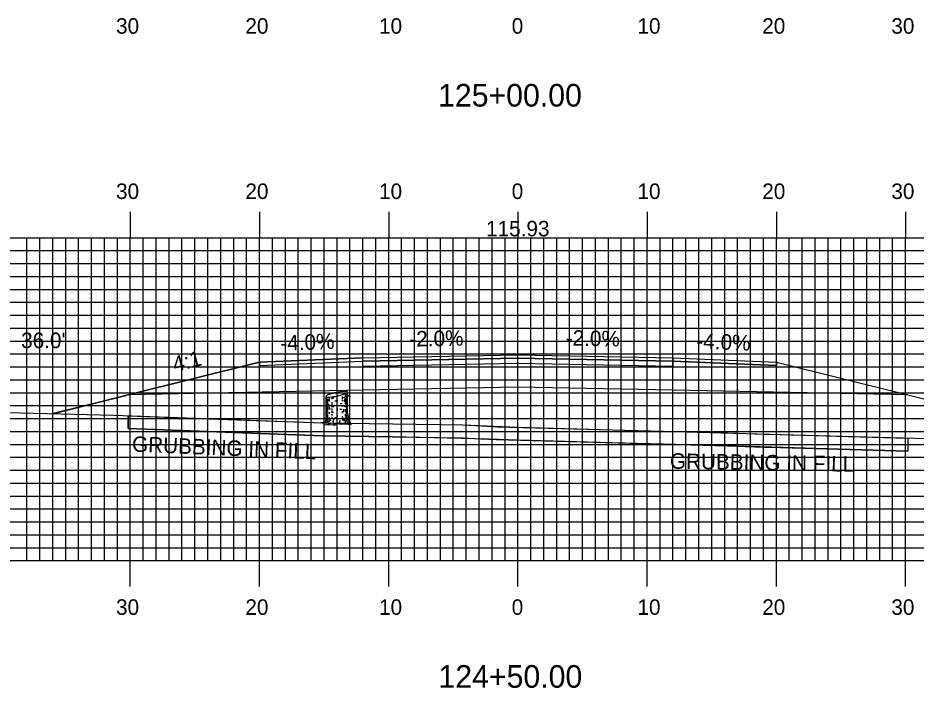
# Model space of a CAD drawing. Extents: x 1772809 to 1773153, y 442591 to 442811.
# Drawn here: x 1772936.4 to 1773005.9, y 442688.8 to 442740.7 of the extents above; entities that cross this region are included whole.
import ezdxf

# ---------------------------------------------------------------- set-up
doc = ezdxf.new("R2010")
doc.units = 0
for name, color, linetype in [('ANNOTATION', 7, 'Continuous'), ('D_Roadway_Centerline', 7, 'Continuous'), ('D_Roadway_Centerline_Text', 7, 'Continuous'), ('D_Roadway_Edge_Shoulder', 7, 'Continuous'), ('D_Roadway_Edge_TW', 7, 'Continuous'), ('D_Roadway_Pavement', 7, 'Continuous'), ('D_Roadway_SlopeLines', 7, 'Continuous'), ('D_Roadway_SubGrade', 7, 'Continuous'), ('D_Text_Standard', 7, 'Continuous'), ('GRUBBING IN FILL', 7, 'Continuous'), ('H_V ANNOTATION', 7, 'Continuous'), ('M_Trees_Conifer_Pay', 7, 'Continuous'), ('MAJOR', 7, 'Continuous'), ('MINOR', 7, 'Continuous'), ('S_Roadway_Centerline', 7, 'Continuous')]:
    doc.layers.add(name, color=color, linetype=linetype)

msp = doc.modelspace()

# ---------------------------------------------------------------- linework, layer by layer
at = {"layer": 'D_Roadway_Centerline'}
msp.add_lwpolyline([(1772939.158, 442710.043), (1772939.401, 442710.104), (1772943.12, 442711.034), (1772944.769, 442711.446), (1772944.946, 442711.49), (1772955.12, 442714.034), (1772963.12, 442714.354), (1772975.119, 442714.594), (1772987.12, 442714.354), (1772995.12, 442714.034), (1773005.294, 442711.49), (1773020.347, 442707.727)], dxfattribs=at)
at = {"layer": 'D_Roadway_Edge_Shoulder'}
for points in [[(1772963.12, 442714.354), (1772955.12, 442714.034), (1772955.12, 442713.784), (1772963.12, 442714.104)], [(1772987.12, 442714.354), (1772995.12, 442714.034), (1772995.12, 442713.784), (1772987.12, 442714.104)]]:
    msp.add_lwpolyline(points, close=True, dxfattribs=at)
at = {"layer": 'D_Roadway_Edge_TW'}
msp.add_lwpolyline([(1772963.12, 442714.104), (1772963.12, 442714.354), (1772975.119, 442714.594), (1772987.12, 442714.354), (1772987.12, 442714.104), (1772975.119, 442714.344)], close=True, dxfattribs=at)
at = {"layer": 'D_Roadway_Pavement'}
msp.add_lwpolyline([(1772963.12, 442713.687), (1772963.12, 442714.104), (1772975.119, 442714.344), (1772987.12, 442714.104), (1772987.12, 442713.687), (1772975.119, 442713.927)], close=True, dxfattribs=at)
at = {"layer": 'D_Roadway_SlopeLines'}
for points in [[(1772955.12, 442714.034), (1772944.946, 442711.49), (1772943.12, 442711.034), (1772939.158, 442710.043)], [(1772995.12, 442714.034), (1773005.294, 442711.49), (1773020.347, 442707.727)]]:
    msp.add_lwpolyline(points, dxfattribs=at)
at = {"layer": 'D_Roadway_SubGrade'}
msp.add_lwpolyline([(1772963.12, 442711.854), (1772944.946, 442711.49), (1772955.12, 442714.034), (1772955.12, 442713.784), (1772963.12, 442714.104), (1772975.119, 442714.344), (1772987.12, 442714.104), (1772995.12, 442713.784), (1772995.12, 442714.034), (1773005.294, 442711.49), (1772987.12, 442711.854), (1772975.119, 442712.094)], close=True, dxfattribs=at)
at = {"layer": 'GRUBBING IN FILL'}
for p, q in [((1772944.946, 442709.881), (1772944.946, 442708.881)), ((1772944.946, 442709.881), (1772944.946, 442708.881)), ((1773005.294, 442708.151), (1773005.294, 442707.151)), ((1773005.294, 442708.151), (1773005.294, 442707.151))]:
    msp.add_line(p, q, dxfattribs=at)
for points in [[(1772944.946, 442709.881), (1772951.924, 442709.628), (1772960.001, 442709.334), (1772965.43, 442709.25), (1772970.86, 442709.165), (1772975.12, 442708.99), (1772975.12, 442707.989), (1772972.856, 442708.067), (1772965.402, 442708.25), (1772959.975, 442708.335), (1772952.461, 442708.608), (1772944.946, 442708.881)], [(1772944.946, 442709.881), (1772951.924, 442709.628), (1772960.001, 442709.334), (1772965.43, 442709.25), (1772970.86, 442709.165), (1772975.12, 442708.99), (1772975.12, 442707.989), (1772972.856, 442708.067), (1772965.402, 442708.25), (1772959.975, 442708.335), (1772952.461, 442708.608), (1772944.946, 442708.881)], [(1772975.12, 442708.99), (1772982.42, 442708.791), (1772992.746, 442708.503), (1773000.682, 442708.278), (1773005.294, 442708.151), (1773005.294, 442707.151), (1772999.92, 442707.299), (1772991.302, 442707.549), (1772982.385, 442707.792), (1772975.12, 442707.989)], [(1772975.12, 442708.99), (1772982.42, 442708.791), (1772992.746, 442708.503), (1773000.682, 442708.278), (1773005.294, 442708.151), (1773005.294, 442707.151), (1772999.92, 442707.299), (1772991.302, 442707.549), (1772982.385, 442707.792), (1772975.12, 442707.989)]]:
    msp.add_lwpolyline(points, close=True, dxfattribs=at)
msp.add_lwpolyline([(1772944.946, 442708.881), (1772959.975, 442708.335), (1772970.829, 442708.166), (1772972.243, 442708.099), (1772973.468, 442708.034), (1772991.302, 442707.549), (1772994.141, 442707.457), (1772994.327, 442707.456), (1772994.546, 442707.446), (1773005.294, 442707.151)], dxfattribs=at)
msp.add_lwpolyline([(1772944.946, 442708.881), (1772959.975, 442708.335), (1772970.829, 442708.166), (1772972.243, 442708.099), (1772973.468, 442708.034), (1772991.302, 442707.549), (1772994.141, 442707.457), (1772994.327, 442707.456), (1772994.546, 442707.446), (1773005.294, 442707.151)], dxfattribs=at)
at = {"layer": 'M_Trees_Conifer_Pay'}
for p, q in [((1772960.269, 442709.656), (1772960.269, 442711.378)), ((1772960.317, 442711.341), (1772960.317, 442710.869)), ((1772960.375, 442711.329), (1772960.375, 442711.232)), ((1772960.375, 442711.158), (1772960.375, 442710.953)), ((1772960.5, 442711.322), (1772960.5, 442711.089)), ((1772960.72, 442711.342), (1772960.72, 442711.174)), ((1772961.126, 442711.11), (1772961.126, 442711.015)), ((1772961.516, 442711.384), (1772961.516, 442711.184)), ((1772961.516, 442711.127), (1772961.516, 442711.038)), ((1772961.744, 442711.58), (1772961.744, 442711.357)), ((1772961.744, 442711.268), (1772961.744, 442711.221)), ((1772961.802, 442711.085), (1772961.75, 442711.026)), ((1772961.862, 442711.641), (1772961.862, 442711.478)), ((1772961.862, 442711.411), (1772961.862, 442711.283)), ((1772961.862, 442711.096), (1772961.862, 442710.76)), ((1772961.933, 442710.066), (1772961.933, 442711.713)), ((1772960.317, 442710.805), (1772960.317, 442710.497)), ((1772960.317, 442710.449), (1772960.317, 442709.957)), ((1772960.375, 442710.896), (1772960.375, 442710.696)), ((1772960.375, 442710.649), (1772960.375, 442710.313)), ((1772960.5, 442711.049), (1772960.5, 442710.974)), ((1772960.5, 442710.571), (1772960.5, 442710.432)), ((1772960.72, 442710.937), (1772960.72, 442710.7)), ((1772960.72, 442710.455), (1772960.72, 442710.303)), ((1772961.126, 442710.497), (1772961.126, 442710.423)), ((1772961.126, 442710.398), (1772961.126, 442710.249)), ((1772961.516, 442710.69), (1772961.516, 442710.585)), ((1772961.744, 442710.886), (1772961.744, 442710.754)), ((1772961.744, 442710.643), (1772961.744, 442710.533)), ((1772961.744, 442710.398), (1772961.744, 442710.256)), ((1772961.862, 442710.723), (1772961.862, 442710.56)), ((1772961.862, 442710.513), (1772961.862, 442710.297)), ((1772960.317, 442709.904), (1772960.317, 442709.656)), ((1772960.375, 442710.26), (1772960.375, 442710.124)), ((1772960.375, 442710.025), (1772960.375, 442709.646)), ((1772960.5, 442710.161), (1772960.5, 442710.019)), ((1772960.5, 442709.757), (1772960.5, 442709.663)), ((1772960.72, 442710.26), (1772960.72, 442710.087)), ((1772960.72, 442709.809), (1772960.72, 442709.656)), ((1772961.126, 442709.957), (1772961.126, 442709.804)), ((1772961.516, 442710.219), (1772961.516, 442710.072)), ((1772961.516, 442709.84), (1772961.516, 442709.751)), ((1772961.744, 442710.029), (1772961.744, 442709.856)), ((1772961.862, 442710.266), (1772961.862, 442710.192)), ((1772961.862, 442710.151), (1772961.862, 442709.978)), ((1772960.5, 442709.263), (1772960.663, 442709.327)), ((1772960.937, 442709.199), (1772960.811, 442709.263))]:
    msp.add_line(p, q, dxfattribs=at)
for points in [[(1772961.717, 442711.174), (1772961.686, 442711.089), (1772961.682, 442711.022), (1772961.713, 442710.958)], [(1772961.75, 442711.211), (1772961.787, 442711.137), (1772961.834, 442711.194), (1772961.892, 442711.262), (1772961.985, 442711.456), (1772962.049, 442711.503), (1772962.08, 442711.51)], [(1772961.765, 442710.958), (1772961.802, 442711.085), (1772961.865, 442711.201), (1772961.896, 442711.268), (1772961.965, 442711.415)], [(1772961.979, 442711.444), (1772962.055, 442711.452), (1772962.127, 442711.353)], [(1772960.449, 442710.684), (1772960.443, 442710.779), (1772960.486, 442710.756), (1772960.486, 442710.661)], [(1772961.588, 442710.285), (1772961.6, 442710.208), (1772961.647, 442710.219), (1772961.635, 442710.385)], [(1772961.933, 442710.066), (1772961.985, 442709.804), (1772962.001, 442709.531), (1772962.059, 442709.406), (1772962.195, 442709.375), (1772961.964, 442709.337), (1772961.964, 442709.337), (1772961.97, 442709.29), (1772962.218, 442709.196), (1772961.943, 442709.212), (1772961.588, 442709.232), (1772961.266, 442709.222), (1772961.273, 442709.304), (1772961.124, 442709.222), (1772960.937, 442709.199), (1772960.962, 442709.131), (1772960.694, 442709.175), (1772960.473, 442709.148), (1772960.181, 442709.165), (1772960.47, 442709.222), (1772960.5, 442709.263), (1772960.338, 442709.321), (1772960.101, 442709.331), (1772959.86, 442709.331), (1772960.202, 442709.389), (1772960.243, 442709.469), (1772960.269, 442709.656)], [(1772961.76, 442709.778), (1772961.834, 442709.673), (1772961.839, 442709.5), (1772961.964, 442709.337)], [(1772961.859, 442709.924), (1772961.865, 442709.778), (1772961.912, 442709.71), (1772961.923, 442709.511)], [(1772960.317, 442709.609), (1772960.296, 442709.531), (1772960.276, 442709.436)], [(1772960.395, 442709.589), (1772960.401, 442709.473), (1772960.348, 442709.385), (1772960.338, 442709.321)], [(1772960.558, 442709.616), (1772960.558, 442709.484), (1772960.47, 442709.385)], [(1772960.784, 442709.375), (1772960.852, 442709.469), (1772960.879, 442709.609)], [(1772961.273, 442709.304), (1772961.347, 442709.446), (1772961.357, 442709.547)], [(1772961.523, 442709.673), (1772961.534, 442709.547), (1772961.608, 442709.504)], [(1772961.802, 442709.284), (1772961.787, 442709.422), (1772961.713, 442709.551)]]:
    msp.add_lwpolyline(points, dxfattribs=at)
for centre, radius, start, end in [((1772960.302, 442711.2), 0.0334, 163.94846, 180), ((1772960.302, 442711.2), 0.0334, 180, 196.05154), ((1772960.301, 442711.377), 0.0314, 156.51582, 169.2194), ((1772960.296, 442711.378), 0.0264, 169.2194, 180.03145), ((1772960.292, 442711.378), 0.0226, 180.03145, 191.7194), ((1772960.292, 442711.378), 0.0226, 191.7194, 203.40735), ((1772960.312, 442711.203), 0.0441, 196.05154, 210), ((1772960.296, 442711.379), 0.0264, 203.40735, 214.2194), ((1772960.32, 442711.368), 0.0527, 146.7194, 156.51582), ((1772960.3, 442711.382), 0.0314, 214.2194, 226.92298), ((1772960.328, 442711.212), 0.0624, 210, 228.74941), ((1772960.345, 442711.352), 0.0817, 132.38868, 146.7194), ((1772960.314, 442711.398), 0.0527, 226.92298, 236.7194), ((1772960.33, 442711.422), 0.0817, 236.7194, 251.05013), ((1772960.4, 442711.294), 0.172, 228.74941, 240), ((1772960.458, 442711.228), 0.251, 124.2194, 132.38868), ((1772960.385, 442711.582), 0.251, 251.05013, 259.2194), ((1772960.599, 442711.639), 0.571, 240, 240.33672), ((1772960.768, 442710.772), 0.802, 108.05939, 124.2194), ((1772960.488, 442712.123), 0.802, 259.2194, 275.37941), ((1772960.599, 442711.639), 0.571, 246.85973, 257.98457), ((1772962.125, 442706.61), 5.179, 101.7194, 108.05939), ((1772960.078, 442716.481), 5.179, 275.37941, 281.7194), ((1772961.102, 442715.39), 4.124, 264.6955, 266.73309), ((1772962.125, 442706.61), 5.179, 95.37941, 101.7194), ((1772960.078, 442716.481), 5.179, 281.7194, 288.05939), ((1772961.102, 442715.39), 4.124, 276.23804, 278.1032), ((1772961.715, 442710.968), 0.802, 79.2194, 95.37941), ((1772961.435, 442712.319), 0.802, 288.05939, 304.2194), ((1772961.603, 442711.872), 0.571, 278.1032, 284.36665), ((1772961.603, 442712.027), 0.571, 284.43166, 292.41325), ((1772961.603, 442711.872), 0.571, 297.0237, 300), ((1772961.818, 442711.51), 0.251, 71.05013, 79.2194), ((1772961.745, 442711.864), 0.251, 304.2194, 312.38868), ((1772961.802, 442711.682), 0.172, 300, 311.25059), ((1772961.802, 442711.527), 0.172, 300, 311.25059), ((1772961.873, 442711.669), 0.0817, 56.7194, 71.05013), ((1772961.858, 442711.739), 0.0817, 312.38868, 326.7194), ((1772961.874, 442711.599), 0.0624, 311.25059, 330), ((1772961.874, 442711.445), 0.0624, 311.25059, 330), ((1772961.889, 442711.694), 0.0527, 46.92298, 56.7194), ((1772961.903, 442711.709), 0.0314, 34.2194, 46.92298), ((1772961.883, 442711.723), 0.0527, 326.7194, 336.51582), ((1772961.89, 442711.59), 0.0441, 330, 343.94846), ((1772961.89, 442711.436), 0.0441, 330, 343.94846), ((1772961.907, 442711.712), 0.0264, 23.40735, 34.2194), ((1772961.902, 442711.714), 0.0314, 336.51582, 349.2194), ((1772961.911, 442711.713), 0.0226, 11.7194, 23.40735), ((1772961.9, 442711.587), 0.0334, 343.94846, 354.21506), ((1772961.9, 442711.433), 0.0334, 343.94846, 354.21506), ((1772961.911, 442711.713), 0.0226, 0.03145, 11.7194), ((1772961.907, 442711.713), 0.0264, 349.2194, 0.03145), ((1772960.302, 442710.753), 0.0334, 163.94846, 180), ((1772960.302, 442710.753), 0.0334, 180, 196.05154), ((1772960.302, 442710.543), 0.0334, 163.94846, 180), ((1772960.302, 442710.543), 0.0334, 180, 196.05154), ((1772960.312, 442710.756), 0.0441, 196.05154, 210), ((1772960.312, 442710.546), 0.0441, 196.05154, 210), ((1772960.328, 442710.765), 0.0624, 210, 228.74941), ((1772960.328, 442710.555), 0.0624, 210, 228.74941), ((1772960.4, 442710.848), 0.172, 228.74941, 240), ((1772960.4, 442710.638), 0.172, 228.74941, 240), ((1772960.599, 442711.193), 0.571, 240, 240.33672), ((1772960.599, 442710.983), 0.571, 240, 246.85973), ((1772960.601, 442711.428), 0.571, 240, 247.05866), ((1772960.599, 442710.983), 0.571, 259.27072, 261.8968), ((1772961.1, 442714.5), 4.124, 261.8968, 263.14738), ((1772961.1, 442714.71), 4.124, 264.08098, 266.66759), ((1772961.1, 442715.157), 4.124, 268.07512, 270), ((1772961.1, 442715.157), 4.124, 270, 270.35814), ((1772961.1, 442714.5), 4.124, 273.14934, 275.45691), ((1772961.102, 442714.946), 4.124, 273.70524, 275.95043), ((1772961.1, 442715.157), 4.124, 275.78493, 277.05584), ((1772961.1, 442714.71), 4.124, 277.61247, 278.1032), ((1772961.601, 442711.193), 0.571, 278.1032, 286.92962), ((1772961.602, 442711.428), 0.571, 284.44928, 297.04285), ((1772961.601, 442711.193), 0.571, 297.18959, 300), ((1772961.601, 442710.983), 0.571, 297.18959, 300), ((1772961.8, 442710.848), 0.172, 300, 311.25059), ((1772961.8, 442710.638), 0.172, 300, 311.25059), ((1772961.873, 442710.765), 0.0624, 311.25059, 330), ((1772961.873, 442710.555), 0.0624, 311.25059, 330), ((1772961.889, 442710.756), 0.0441, 330, 343.94846), ((1772961.889, 442710.546), 0.0441, 330, 343.94846), ((1772961.899, 442710.753), 0.0334, 343.94846, 354.21506), ((1772961.899, 442710.543), 0.0334, 343.94846, 354.21506), ((1772961.9, 442710.989), 0.0334, 343.94846, 354.21506), ((1772960.302, 442710.306), 0.0334, 163.94846, 180), ((1772960.302, 442710.306), 0.0334, 180, 196.05154), ((1772960.302, 442710.108), 0.0334, 163.94846, 180), ((1772960.302, 442709.913), 0.0334, 163.94846, 180), ((1772960.302, 442709.913), 0.0334, 180, 196.05154), ((1772960.302, 442709.693), 0.0334, 163.94846, 180), ((1772960.302, 442709.693), 0.0334, 180, 196.05154), ((1772960.312, 442710.309), 0.0441, 196.05154, 210), ((1772960.312, 442709.916), 0.0441, 196.05154, 210), ((1772960.328, 442710.318), 0.0624, 210, 228.74941), ((1772960.328, 442709.925), 0.0624, 210, 228.74941), ((1772960.4, 442710.401), 0.172, 228.74941, 240), ((1772960.4, 442710.008), 0.172, 228.74941, 240), ((1772960.599, 442710.746), 0.571, 240, 246.85973), ((1772960.589, 442710.554), 0.571, 241.23686, 248.02677), ((1772960.599, 442710.353), 0.571, 240, 246.85973), ((1772961.1, 442714.066), 4.124, 263.49906, 265.83975), ((1772961.1, 442714.263), 4.124, 264.71603, 266.31934), ((1772961.1, 442713.87), 4.124, 267.81166, 270), ((1772961.1, 442714.5), 4.124, 270, 270.35814), ((1772961.1, 442713.87), 4.124, 270, 270.13279), ((1772961.1, 442713.87), 4.124, 275.78493, 276.78961), ((1772961.601, 442710.746), 0.571, 285.39827, 297.18959), ((1772961.601, 442710.353), 0.571, 288.50673, 297.27208), ((1772961.601, 442710.548), 0.571, 289.29072, 300), ((1772961.8, 442710.203), 0.172, 300, 311.25059), ((1772961.873, 442710.121), 0.0624, 311.25059, 330), ((1772961.889, 442710.111), 0.0441, 330, 343.94846), ((1772961.899, 442710.108), 0.0334, 343.94846, 354.21506), ((1772961.899, 442709.693), 0.0334, 343.94846, 354.21506), ((1772960.312, 442709.696), 0.0441, 196.05154, 210), ((1772960.328, 442709.705), 0.0624, 210, 228.74941), ((1772960.4, 442709.787), 0.172, 228.74941, 240), ((1772960.599, 442710.132), 0.571, 240, 244.53138), ((1772961.1, 442713.65), 4.124, 262.44379, 263.51202), ((1772961.1, 442713.65), 4.124, 277.36842, 278.1032), ((1772961.601, 442710.132), 0.571, 278.1032, 281.63703), ((1772961.8, 442709.787), 0.172, 300, 311.25059), ((1772961.873, 442709.705), 0.0624, 311.25059, 330), ((1772961.889, 442709.696), 0.0441, 330, 343.94846)]:
    msp.add_arc(centre, radius, start, end, dxfattribs=at)
at = {"layer": 'MAJOR'}
for p, q in [((1772945.12, 442725.669), (1772945.12, 442723.665)), ((1772955.12, 442725.669), (1772955.12, 442723.665)), ((1772965.12, 442725.669), (1772965.12, 442723.665)), ((1772975.12, 442725.669), (1772975.12, 442723.665)), ((1772985.12, 442725.669), (1772985.12, 442723.665)), ((1772995.12, 442725.669), (1772995.12, 442723.665)), ((1773005.12, 442725.669), (1773005.12, 442723.665)), ((1772835.12, 442723.665), (1773115.12, 442723.665)), ((1772835.12, 442723.665), (1773115.12, 442723.665)), ((1772945.12, 442698.665), (1772945.12, 442723.665)), ((1772955.12, 442698.665), (1772955.12, 442723.665)), ((1772965.12, 442698.665), (1772965.12, 442723.665)), ((1772975.12, 442698.665), (1772975.12, 442723.665)), ((1772985.12, 442698.665), (1772985.12, 442723.665)), ((1772995.12, 442698.665), (1772995.12, 442723.665)), ((1773005.12, 442698.665), (1773005.12, 442723.665)), ((1772835.12, 442718.665), (1773115.12, 442718.665)), ((1772835.12, 442713.665), (1773115.12, 442713.665)), ((1772835.12, 442708.665), (1773115.12, 442708.665)), ((1772835.12, 442703.665), (1773115.12, 442703.665)), ((1772835.12, 442698.665), (1773115.12, 442698.665)), ((1772835.12, 442698.665), (1773115.12, 442698.665)), ((1772945.12, 442696.661), (1772945.12, 442698.665)), ((1772955.12, 442696.661), (1772955.12, 442698.665)), ((1772965.12, 442696.661), (1772965.12, 442698.665)), ((1772975.12, 442696.661), (1772975.12, 442698.665)), ((1772985.12, 442696.661), (1772985.12, 442698.665)), ((1772995.12, 442696.661), (1772995.12, 442698.665)), ((1773005.12, 442696.661), (1773005.12, 442698.665))]:
    msp.add_line(p, q, dxfattribs=at)
at = {"layer": 'MINOR'}
for p, q in [((1772937.12, 442698.665), (1772937.12, 442723.665)), ((1772938.12, 442698.665), (1772938.12, 442723.665)), ((1772939.12, 442698.665), (1772939.12, 442723.665)), ((1772940.12, 442698.665), (1772940.12, 442723.665)), ((1772941.12, 442698.665), (1772941.12, 442723.665)), ((1772942.12, 442698.665), (1772942.12, 442723.665)), ((1772943.12, 442698.665), (1772943.12, 442723.665)), ((1772944.12, 442698.665), (1772944.12, 442723.665)), ((1772946.12, 442698.665), (1772946.12, 442723.665)), ((1772947.12, 442698.665), (1772947.12, 442723.665)), ((1772948.12, 442698.665), (1772948.12, 442723.665)), ((1772949.12, 442698.665), (1772949.12, 442723.665)), ((1772950.12, 442698.665), (1772950.12, 442723.665)), ((1772951.12, 442698.665), (1772951.12, 442723.665)), ((1772952.12, 442698.665), (1772952.12, 442723.665)), ((1772953.12, 442698.665), (1772953.12, 442723.665)), ((1772954.12, 442698.665), (1772954.12, 442723.665)), ((1772956.12, 442698.665), (1772956.12, 442723.665)), ((1772957.12, 442698.665), (1772957.12, 442723.665)), ((1772958.12, 442698.665), (1772958.12, 442723.665)), ((1772959.12, 442698.665), (1772959.12, 442723.665)), ((1772960.12, 442698.665), (1772960.12, 442723.665)), ((1772961.12, 442698.665), (1772961.12, 442723.665)), ((1772962.12, 442698.665), (1772962.12, 442723.665)), ((1772963.12, 442698.665), (1772963.12, 442723.665)), ((1772964.12, 442698.665), (1772964.12, 442723.665)), ((1772966.12, 442698.665), (1772966.12, 442723.665)), ((1772967.12, 442698.665), (1772967.12, 442723.665)), ((1772968.12, 442698.665), (1772968.12, 442723.665)), ((1772969.12, 442698.665), (1772969.12, 442723.665)), ((1772970.12, 442698.665), (1772970.12, 442723.665)), ((1772971.12, 442698.665), (1772971.12, 442723.665)), ((1772972.12, 442698.665), (1772972.12, 442723.665)), ((1772973.12, 442698.665), (1772973.12, 442723.665)), ((1772974.12, 442698.665), (1772974.12, 442723.665)), ((1772976.12, 442698.665), (1772976.12, 442723.665)), ((1772977.12, 442698.665), (1772977.12, 442723.665)), ((1772978.12, 442698.665), (1772978.12, 442723.665)), ((1772979.12, 442698.665), (1772979.12, 442723.665)), ((1772980.12, 442698.665), (1772980.12, 442723.665)), ((1772981.12, 442698.665), (1772981.12, 442723.665)), ((1772982.12, 442698.665), (1772982.12, 442723.665)), ((1772983.12, 442698.665), (1772983.12, 442723.665)), ((1772984.12, 442698.665), (1772984.12, 442723.665)), ((1772986.12, 442698.665), (1772986.12, 442723.665)), ((1772987.12, 442698.665), (1772987.12, 442723.665)), ((1772988.12, 442698.665), (1772988.12, 442723.665)), ((1772989.12, 442698.665), (1772989.12, 442723.665)), ((1772990.12, 442698.665), (1772990.12, 442723.665)), ((1772991.12, 442698.665), (1772991.12, 442723.665)), ((1772992.12, 442698.665), (1772992.12, 442723.665)), ((1772993.12, 442698.665), (1772993.12, 442723.665)), ((1772994.12, 442698.665), (1772994.12, 442723.665)), ((1772996.12, 442698.665), (1772996.12, 442723.665)), ((1772997.12, 442698.665), (1772997.12, 442723.665)), ((1772998.12, 442698.665), (1772998.12, 442723.665)), ((1772999.12, 442698.665), (1772999.12, 442723.665)), ((1773000.12, 442698.665), (1773000.12, 442723.665)), ((1773001.12, 442698.665), (1773001.12, 442723.665)), ((1773002.12, 442698.665), (1773002.12, 442723.665)), ((1773003.12, 442698.665), (1773003.12, 442723.665)), ((1773004.12, 442698.665), (1773004.12, 442723.665)), ((1772835.12, 442722.665), (1773115.12, 442722.665)), ((1772835.12, 442721.665), (1773115.12, 442721.665)), ((1772835.12, 442720.665), (1773115.12, 442720.665)), ((1772835.12, 442719.665), (1773115.12, 442719.665)), ((1772835.12, 442717.665), (1773115.12, 442717.665)), ((1772835.12, 442716.665), (1773115.12, 442716.665)), ((1772835.12, 442715.665), (1773115.12, 442715.665)), ((1772835.12, 442714.665), (1773115.12, 442714.665)), ((1772835.12, 442712.665), (1773115.12, 442712.665)), ((1772835.12, 442711.665), (1773115.12, 442711.665)), ((1772835.12, 442710.665), (1773115.12, 442710.665)), ((1772835.12, 442709.665), (1773115.12, 442709.665)), ((1772835.12, 442707.665), (1773115.12, 442707.665)), ((1772835.12, 442706.665), (1773115.12, 442706.665)), ((1772835.12, 442705.665), (1773115.12, 442705.665)), ((1772835.12, 442704.665), (1773115.12, 442704.665)), ((1772835.12, 442702.665), (1773115.12, 442702.665)), ((1772835.12, 442701.665), (1773115.12, 442701.665)), ((1772835.12, 442700.665), (1773115.12, 442700.665)), ((1772835.12, 442699.665), (1773115.12, 442699.665))]:
    msp.add_line(p, q, dxfattribs=at)
at = {"layer": 'S_Roadway_Centerline'}
msp.add_lwpolyline([(1772930.628, 442710.207), (1772936.627, 442710.11), (1772943.848, 442709.921), (1772960.001, 442709.334), (1772970.86, 442709.165), (1772972.293, 442709.098), (1772973.509, 442709.034), (1772991.332, 442708.548), (1772994.16, 442708.457), (1772994.352, 442708.455), (1772994.581, 442708.446), (1773006.783, 442708.11), (1773017.015, 442707.813), (1773019.541, 442707.75), (1773022.485, 442707.665), (1773038.067, 442706.998), (1773042.223, 442706.935), (1773048.141, 442706.881)], dxfattribs=at)

# ---------------------------------------------------------------- texts
at = {"layer": 'ANNOTATION'}
for s, rotation, p in [('-4.0%', 2.29076, (1772956.752, 442714.901)), ('-2.0%', 1.1458, (1772966.726, 442715.227)), ('-2.0%', 358.85427, (1772978.806, 442715.321)), ('-4.0%', 357.70946, (1772988.911, 442715.084)), ('4:1', 14.03896, (1772948.569, 442713.258))]:
    msp.add_text(s, height=1.2, rotation=rotation, dxfattribs=at).set_placement(p)
at = {"layer": 'D_Roadway_Centerline'}
for s, p in [('C', (1772975.114, 442714.594)), ('L', (1772975.119, 442714.587))]:
    msp.add_text(s, height=0.0146, dxfattribs=at).set_placement(p)
at = {"layer": 'D_Roadway_Centerline_Text'}
msp.add_text('115.93', height=1.2, dxfattribs=at).set_placement((1772972.653, 442723.773))
at = {"layer": 'D_Text_Standard'}
msp.add_text("36.0'", height=1.2, dxfattribs=at).set_placement((1772936.671, 442715.12))
at = {"layer": 'GRUBBING IN FILL'}
for rotation, p in [(357.57187, (1772945.235, 442707.106)), (359.01917, (1772986.871, 442705.785))]:
    msp.add_text('GRUBBING IN FILL', height=1.2, rotation=rotation, dxfattribs=at).set_placement(p)
at = {"layer": 'H_V ANNOTATION'}
for s, height, p in [('30', 1.2, (1772944.017, 442739.465)), ('20', 1.2, (1772954.028, 442739.465)), ('10', 1.2, (1772964.37, 442739.465)), ('0', 1.2, (1772974.638, 442739.465)), ('10', 1.2, (1772984.37, 442739.465)), ('20', 1.2, (1772994.028, 442739.465)), ('30', 1.2, (1773004.017, 442739.465)), ('125+00.00', 1.75, (1772968.94, 442733.821)), ('30', 1.2, (1772944.017, 442726.665)), ('20', 1.2, (1772954.028, 442726.665)), ('10', 1.2, (1772964.37, 442726.665)), ('0', 1.2, (1772974.638, 442726.665)), ('10', 1.2, (1772984.37, 442726.665)), ('20', 1.2, (1772994.028, 442726.665)), ('30', 1.2, (1773004.017, 442726.665)), ('30', 1.2, (1772944.017, 442694.465)), ('20', 1.2, (1772954.028, 442694.465)), ('10', 1.2, (1772964.37, 442694.465)), ('0', 1.2, (1772974.638, 442694.465)), ('10', 1.2, (1772984.37, 442694.465)), ('20', 1.2, (1772994.028, 442694.465)), ('30', 1.2, (1773004.017, 442694.465)), ('124+50.00', 1.75, (1772968.971, 442688.821))]:
    msp.add_text(s, height=height, dxfattribs=at).set_placement(p)

doc.saveas('drawing.dxf')
